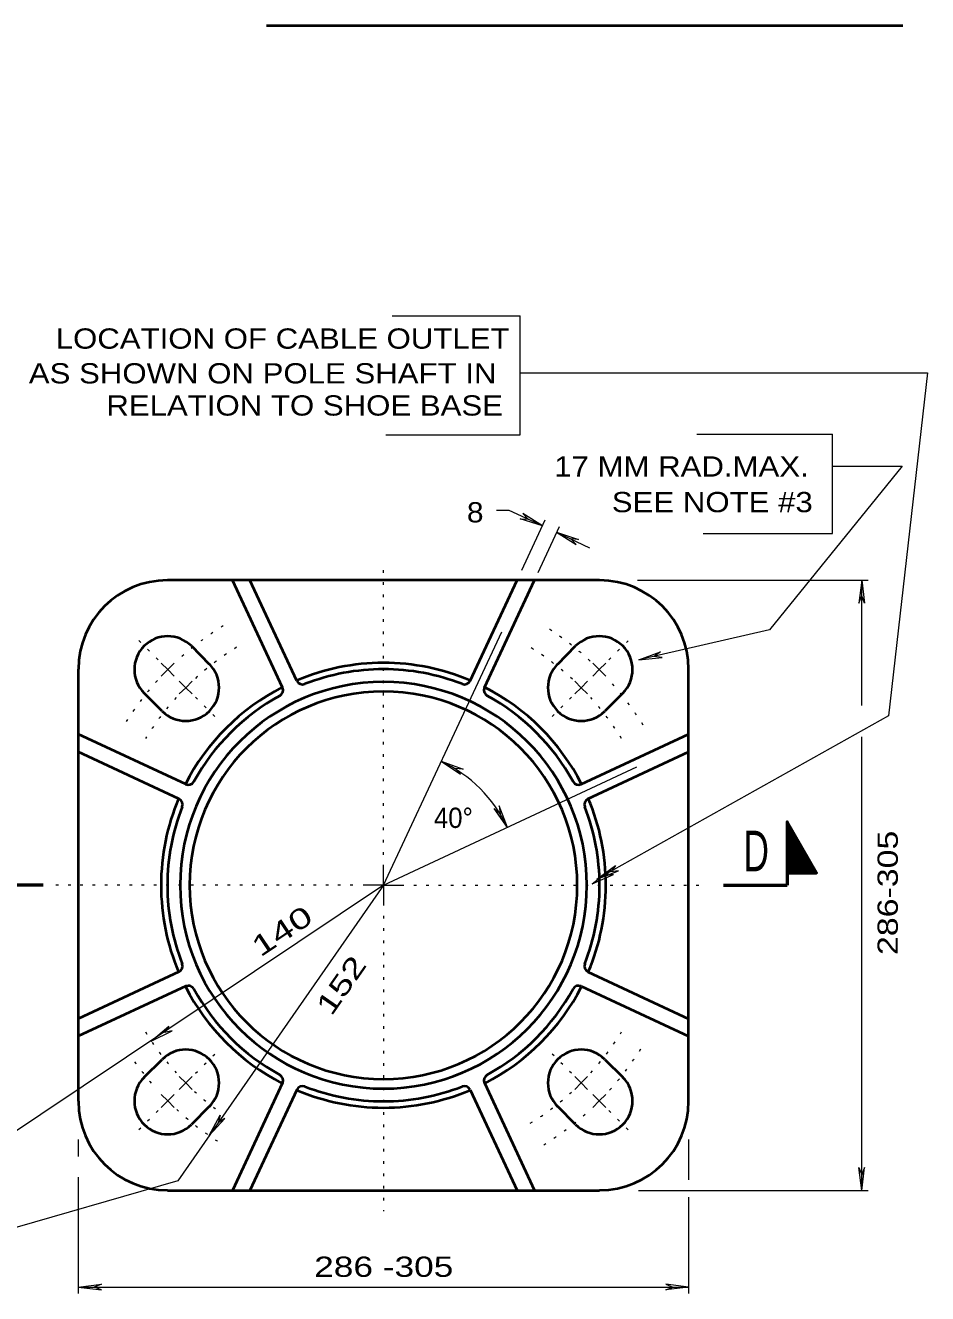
# Model space of a CAD drawing. Extents: x 312583 to 312854, y 144418 to 144597.
# Drawn here: x 312774.81 to 312808.64, y 144500.47 to 144548.02 of the extents above; entities that cross this region are included whole.
import ezdxf
from ezdxf.enums import TextEntityAlignment as Align

# ---------------------------------------------------------------- set-up
doc = ezdxf.new("R2010")
doc.units = 0
doc.header["$LTSCALE"] = 0.3
doc.linetypes.add('DOTTED', pattern=[1.5, 0.3, -1.2])
doc.layers.add('1', color=7, linetype='Continuous', lineweight=35)

msp = doc.modelspace()

# ---------------------------------------------------------------- linework, layer by layer
at = {"layer": '1', "lineweight": 40}
for p, q in [((312783.8489, 144548.0241), (312807.7021, 144548.0241)), ((312788.233, 144527.2141), (312780.1352, 144527.2141)), ((312784.451, 144523.1958), (312782.5752, 144527.2141)), ((312784.9924, 144523.4474), (312783.231, 144527.2141)), ((312796.3384, 144527.2141), (312788.233, 144527.2141)), ((312791.4812, 144523.4474), (312793.2426, 144527.2141)), ((312792.0226, 144523.1958), (312793.8984, 144527.2141)), ((312781.035, 144524.7512), (312781.706, 144524.0726)), ((312794.7676, 144524.0726), (312795.4386, 144524.7512)), ((312776.7955, 144523.882), (312776.7955, 144515.7766)), ((312799.6705, 144515.7766), (312799.6705, 144523.882)), ((312779.937, 144522.3036), (312779.266, 144522.9822)), ((312797.2076, 144522.9822), (312796.5366, 144522.3036)), ((312780.8215, 144519.5662), (312776.7955, 144521.442)), ((312795.6521, 144519.5662), (312799.6705, 144521.442)), ((312780.5699, 144519.0249), (312776.7955, 144520.7786)), ((312795.9038, 144519.0249), (312799.6705, 144520.7786)), ((312776.7955, 144515.7766), (312776.7955, 144507.6789)), ((312799.6705, 144507.6789), (312799.6705, 144515.7766)), ((312780.5699, 144512.5284), (312776.7955, 144510.7746)), ((312795.9038, 144512.5284), (312799.6705, 144510.7746)), ((312780.8215, 144511.9946), (312776.7955, 144510.1189)), ((312795.6521, 144511.9946), (312799.6705, 144510.1189)), ((312779.266, 144508.5786), (312779.937, 144509.2496)), ((312796.5366, 144509.2496), (312797.2076, 144508.5786)), ((312784.451, 144508.3651), (312782.5752, 144504.3391)), ((312784.9924, 144508.1059), (312783.231, 144504.3391)), ((312791.4812, 144508.1059), (312793.2426, 144504.3391)), ((312792.0226, 144508.3651), (312793.8984, 144504.3391)), ((312781.706, 144507.4806), (312781.035, 144506.8096)), ((312795.4386, 144506.8096), (312794.7676, 144507.4806)), ((312780.1352, 144504.3391), (312788.233, 144504.3391)), ((312788.233, 144504.3391), (312796.3384, 144504.3391))]:
    msp.add_line(p, q, dxfattribs=at)
at = {"layer": '1', "lineweight": 13}
for p, q in [((312788.5564, 144537.1328), (312793.3601, 144537.1328)), ((312793.3601, 144532.6645), (312793.3601, 144537.1328)), ((312793.3601, 144534.9992), (312808.6375, 144534.9992)), ((312788.3277, 144532.6645), (312793.3601, 144532.6645)), ((312799.9908, 144532.6965), (312805.069, 144532.6965)), ((312805.069, 144528.9679), (312805.069, 144532.6965)), ((312792.9529, 144529.8371), (312792.4725, 144529.8371)), ((312794.1958, 144529.2576), (312792.9529, 144529.8371)), ((312793.3646, 144529.5245), (312793.662, 144529.5092)), ((312794.1958, 144529.2576), (312793.3646, 144529.5245)), ((312793.418, 144527.5954), (312794.3025, 144529.4864)), ((312793.4561, 144529.7228), (312793.662, 144529.5092)), ((312794.1958, 144529.2576), (312793.4561, 144529.7228)), ((312794.0356, 144527.5039), (312794.8362, 144529.2348)), ((312794.7219, 144529.0136), (312795.9648, 144528.4341)), ((312794.7219, 144529.0136), (312795.553, 144528.7468)), ((312794.7219, 144529.0136), (312795.4615, 144528.5561)), ((312800.2271, 144528.9679), (312805.069, 144528.9679)), ((312795.553, 144528.7468), (312795.2556, 144528.7696)), ((312795.4615, 144528.5561), (312795.2556, 144528.7696)), ((312797.7642, 144527.2141), (312806.411, 144527.2141)), ((312806.167, 144527.2141), (312806.0602, 144526.3525)), ((312806.167, 144527.2141), (312806.2738, 144526.3525)), ((312806.167, 144522.5171), (312806.167, 144527.2141)), ((312806.0602, 144526.3525), (312806.167, 144526.627)), ((312806.2738, 144526.3525), (312806.167, 144526.627)), ((312788.233, 144515.7766), (312792.6708, 144525.2774)), ((312780.1505, 144523.8668), (312779.9065, 144524.1108)), ((312780.1505, 144523.8668), (312780.3945, 144524.1108)), ((312796.3231, 144523.8668), (312796.0868, 144524.1108)), ((312796.3231, 144523.8668), (312796.5671, 144524.1108)), ((312797.81, 144524.2328), (312798.6259, 144524.5301)), ((312797.81, 144524.2328), (312798.6792, 144524.3166)), ((312798.6259, 144524.5301), (312798.3819, 144524.3624)), ((312798.6792, 144524.3166), (312798.3819, 144524.3624)), ((312780.1505, 144523.8668), (312779.9065, 144523.6228)), ((312780.1505, 144523.8668), (312780.3945, 144523.6228)), ((312796.3231, 144523.8668), (312796.0868, 144523.6228)), ((312796.3231, 144523.8668), (312796.5671, 144523.6228)), ((312780.8215, 144523.1881), (312780.5775, 144523.4321)), ((312780.8215, 144523.1881), (312780.5775, 144522.9518)), ((312780.8215, 144523.1881), (312781.0655, 144523.4321)), ((312780.8215, 144523.1881), (312781.0655, 144522.9518)), ((312795.6521, 144523.1881), (312795.4081, 144523.4321)), ((312795.6521, 144523.1881), (312795.4081, 144522.9518)), ((312795.6521, 144523.1881), (312795.8885, 144523.4321)), ((312795.6521, 144523.1881), (312795.8885, 144522.9518)), ((312806.167, 144504.3391), (312806.167, 144521.3429)), ((312790.3985, 144520.4279), (312791.1229, 144519.9399)), ((312790.3985, 144520.4279), (312791.222, 144520.1305)), ((312788.233, 144515.7766), (312797.7414, 144520.2144)), ((312791.1229, 144519.9399), (312790.9246, 144520.1534)), ((312791.222, 144520.1305), (312790.9246, 144520.1534)), ((312792.381, 144518.6589), (312792.6098, 144518.4606)), ((312792.8842, 144517.9421), (312792.381, 144518.6589)), ((312792.5716, 144518.758), (312792.6098, 144518.4606)), ((312792.8842, 144517.9421), (312792.5716, 144518.758)), ((312788.233, 144515.7766), (312788.233, 144516.5391)), ((312796.2392, 144516.0054), (312796.9408, 144516.5162)), ((312796.9408, 144516.5162), (312796.7578, 144516.2875)), ((312796.0639, 144515.83), (312796.7425, 144516.3714)), ((312796.0639, 144515.83), (312796.8569, 144516.1884)), ((312796.2392, 144516.0054), (312797.0475, 144516.3256)), ((312796.7425, 144516.3714), (312796.5671, 144516.135)), ((312796.8569, 144516.1884), (312796.5671, 144516.135)), ((312797.0475, 144516.3256), (312796.7578, 144516.2875)), ((312788.233, 144515.7766), (312773.6388, 144506.0166)), ((312788.233, 144515.7766), (312780.5318, 144504.6975)), ((312788.233, 144515.7766), (312787.4705, 144515.7766)), ((312788.233, 144515.7766), (312788.9955, 144515.7766)), ((312788.233, 144515.7766), (312788.233, 144515.0141)), ((312779.5329, 144509.9282), (312780.1886, 144510.5001)), ((312779.5329, 144509.9282), (312780.3106, 144510.3248)), ((312780.1886, 144510.5001), (312780.0209, 144510.2561)), ((312780.3106, 144510.3248), (312780.0209, 144510.2561)), ((312780.8215, 144508.3651), (312780.5775, 144508.6091)), ((312780.8215, 144508.3651), (312781.0655, 144508.6091)), ((312795.6521, 144508.3651), (312795.4081, 144508.6091)), ((312795.6521, 144508.3651), (312795.8885, 144508.6091)), ((312780.1505, 144507.6941), (312779.9065, 144507.9305)), ((312780.1505, 144507.6941), (312780.3945, 144507.9305)), ((312780.8215, 144508.3651), (312780.5775, 144508.1211)), ((312780.8215, 144508.3651), (312781.0655, 144508.1211)), ((312795.6521, 144508.3651), (312795.4081, 144508.1211)), ((312795.6521, 144508.3651), (312795.8885, 144508.1211)), ((312796.3231, 144507.6941), (312796.0868, 144507.9305)), ((312796.3231, 144507.6941), (312796.5671, 144507.9305)), ((312780.1505, 144507.6941), (312779.9065, 144507.4501)), ((312780.1505, 144507.6941), (312780.3945, 144507.4501)), ((312796.3231, 144507.6941), (312796.0868, 144507.4501)), ((312796.3231, 144507.6941), (312796.5671, 144507.4501)), ((312781.706, 144506.3902), (312782.1101, 144507.1604)), ((312781.706, 144506.3902), (312782.2855, 144507.0384)), ((312782.1101, 144507.1604), (312782.0415, 144506.8706)), ((312782.2855, 144507.0384), (312782.0415, 144506.8706)), ((312776.7955, 144506.2454), (312776.7955, 144505.6049)), ((312799.6705, 144506.2454), (312799.6705, 144504.728)), ((312806.0602, 144505.2008), (312806.167, 144504.9262)), ((312806.167, 144504.3391), (312806.0602, 144505.2008)), ((312806.2738, 144505.2008), (312806.167, 144504.9262)), ((312806.167, 144504.3391), (312806.2738, 144505.2008)), ((312780.5318, 144504.6975), (312773.6388, 144502.7074)), ((312776.7955, 144504.8348), (312776.7955, 144500.4656)), ((312797.7948, 144504.3391), (312806.411, 144504.3391)), ((312799.6705, 144504.0799), (312799.6705, 144500.4656)), ((312776.7955, 144500.7096), (312777.6648, 144500.8164)), ((312777.6648, 144500.8164), (312777.3902, 144500.7096)), ((312798.8165, 144500.8164), (312799.091, 144500.7096)), ((312799.6705, 144500.7096), (312798.8165, 144500.8164)), ((312776.7955, 144500.7096), (312799.6705, 144500.7096)), ((312776.7955, 144500.7096), (312777.6648, 144500.6029)), ((312777.6648, 144500.6029), (312777.3902, 144500.7096)), ((312798.8165, 144500.6029), (312799.091, 144500.7096)), ((312799.6705, 144500.7096), (312798.8165, 144500.6029))]:
    msp.add_line(p, q, dxfattribs=at)
at = {"layer": '1', "linetype": 'DOTTED', "lineweight": 13}
for p, q in [((312788.233, 144516.9204), (312788.233, 144527.8851)), ((312779.7845, 144524.2328), (312779.022, 144524.9952)), ((312796.6891, 144524.2328), (312797.4592, 144524.9952)), ((312781.1875, 144522.8298), (312782.0491, 144521.9681)), ((312795.2861, 144522.8298), (312794.4245, 144521.9681)), ((312787.0892, 144515.7766), (312775.9262, 144515.7766)), ((312789.3768, 144515.7766), (312800.3262, 144515.7766)), ((312788.233, 144514.6329), (312788.233, 144503.5538)), ((312781.1875, 144508.7311), (312782.0491, 144509.5851)), ((312795.2861, 144508.7311), (312794.4245, 144509.5851)), ((312779.7845, 144507.3281), (312779.022, 144506.558)), ((312796.6891, 144507.3281), (312797.4592, 144506.558))]:
    msp.add_line(p, q, dxfattribs=at)
at = {"layer": '1'}
for p, q in [((312803.3686, 144518.1404), (312803.3839, 144518.1404)), ((312803.3686, 144518.1099), (312803.3915, 144518.1175)), ((312803.3686, 144518.0794), (312803.4068, 144518.1022)), ((312803.3686, 144518.0565), (312803.4144, 144518.0794)), ((312803.3686, 144518.026), (312803.4296, 144518.0565)), ((312803.3686, 144518.0031), (312803.4372, 144518.0412)), ((312803.3686, 144517.9726), (312803.4525, 144518.0184)), ((312803.3686, 144517.9421), (312803.4601, 144517.9955)), ((312803.3686, 144517.9116), (312803.4754, 144517.9802)), ((312803.3686, 144517.8888), (312803.483, 144517.9574)), ((312803.3686, 144517.8659), (312803.4982, 144517.9345)), ((312803.3686, 144517.8354), (312803.5059, 144517.9116)), ((312803.3686, 144517.8125), (312803.5211, 144517.8964)), ((312803.3686, 144517.782), (312803.5364, 144517.8735)), ((312803.3686, 144517.7515), (312803.544, 144517.8506)), ((312803.3686, 144517.721), (312803.5592, 144517.8354)), ((312803.3686, 144517.6981), (312803.5745, 144517.8125)), ((312803.3686, 144517.6676), (312803.5821, 144517.7896)), ((312803.3686, 144517.6448), (312803.5974, 144517.7744)), ((312803.3686, 144517.6142), (312803.605, 144517.7515)), ((312803.3686, 144517.5838), (312803.6202, 144517.7286)), ((312803.3686, 144517.5609), (312803.6279, 144517.7134)), ((312803.3686, 144517.5304), (312803.6431, 144517.6829)), ((312803.3686, 144517.5075), (312803.6508, 144517.6676)), ((312803.3686, 144517.477), (312803.666, 144517.6448)), ((312803.3686, 144517.4465), (312803.6736, 144517.6219)), ((312803.3686, 144517.4236), (312803.6889, 144517.6066)), ((312803.3686, 144517.3931), (312803.6965, 144517.5838)), ((312803.3686, 144517.3702), (312803.7118, 144517.5609)), ((312803.3686, 144517.3398), (312803.727, 144517.5456)), ((312803.3686, 144517.3169), (312803.7346, 144517.5228)), ((312803.3686, 144517.2864), (312803.7499, 144517.4999)), ((312803.3686, 144517.2559), (312803.7651, 144517.4846)), ((312803.3686, 144517.2254), (312803.7728, 144517.4618)), ((312803.3686, 144517.2025), (312803.788, 144517.4389)), ((312803.3686, 144517.1796), (312803.7956, 144517.416)), ((312803.3686, 144517.1491), (312803.8109, 144517.4008)), ((312803.3686, 144517.1186), (312803.8185, 144517.3779)), ((312803.3686, 144517.0958), (312803.8338, 144517.355)), ((312803.3686, 144517.0652), (312803.8414, 144517.3398)), ((312803.3686, 144517.0348), (312803.8566, 144517.3169)), ((312803.3686, 144517.0119), (312803.8642, 144517.294)), ((312803.3686, 144516.9814), (312803.8795, 144517.2788)), ((312803.3686, 144516.9509), (312803.8871, 144517.2559)), ((312803.3686, 144516.928), (312803.9024, 144517.233)), ((312803.3686, 144516.8746), (312803.9252, 144517.1872)), ((312803.3686, 144516.8441), (312803.9405, 144517.172)), ((312803.3686, 144516.8212), (312803.9481, 144517.1491)), ((312803.3686, 144516.7908), (312803.9634, 144517.1262)), ((312803.3686, 144516.7602), (312803.971, 144517.111)), ((312803.3686, 144516.7298), (312803.9862, 144517.0881)), ((312803.3686, 144516.7069), (312803.9939, 144517.0652)), ((312803.3686, 144516.684), (312804.0091, 144517.05)), ((312803.3686, 144516.623), (312804.032, 144517.0042)), ((312803.3686, 144516.6001), (312804.0396, 144516.989)), ((312803.3686, 144516.5696), (312804.0549, 144516.9661)), ((312803.3762, 144516.8975), (312803.9176, 144517.2178)), ((312803.3762, 144516.6535), (312804.0168, 144517.0271)), ((312803.3686, 144516.5391), (312804.0701, 144516.9432)), ((312803.3686, 144516.5162), (312804.0778, 144516.9204)), ((312803.3686, 144516.4858), (312804.093, 144516.9051)), ((312803.3686, 144516.4552), (312804.1082, 144516.8822)), ((312803.3686, 144516.379), (312804.1388, 144516.8212)), ((312803.3686, 144516.3485), (312804.154, 144516.7984)), ((312803.3686, 144516.3256), (312804.1616, 144516.7831)), ((312803.3686, 144516.2951), (312804.1769, 144516.7602)), ((312803.3686, 144516.2646), (312804.1845, 144516.7374)), ((312803.3762, 144516.4324), (312804.1159, 144516.8594)), ((312803.3762, 144516.4019), (312804.1311, 144516.8441)), ((312803.3915, 144516.2494), (312804.1998, 144516.7221)), ((312803.4449, 144516.2494), (312804.2074, 144516.6916)), ((312803.483, 144516.2494), (312804.2226, 144516.6764)), ((312803.5364, 144516.2494), (312804.2302, 144516.6535)), ((312803.5821, 144516.2494), (312804.2455, 144516.6306)), ((312803.6279, 144516.2494), (312804.2608, 144516.6154)), ((312803.6736, 144516.2494), (312804.2684, 144516.5925)), ((312803.727, 144516.2494), (312804.2836, 144516.5696)), ((312803.7728, 144516.2494), (312804.2989, 144516.5544)), ((312803.8185, 144516.2494), (312804.3065, 144516.5315)), ((312803.8719, 144516.2494), (312804.3218, 144516.5162)), ((312803.9176, 144516.2494), (312804.3294, 144516.4934)), ((312803.9634, 144516.2494), (312804.3446, 144516.4705)), ((312804.0168, 144516.2494), (312804.3522, 144516.4552)), ((312804.0625, 144516.2494), (312804.3675, 144516.4248)), ((312804.1082, 144516.2494), (312804.3751, 144516.4095)), ((312804.154, 144516.2494), (312804.3904, 144516.3866)), ((312804.2074, 144516.2494), (312804.398, 144516.3638)), ((312804.2455, 144516.2494), (312804.4132, 144516.3485)), ((312804.2989, 144516.2494), (312804.4209, 144516.3256)), ((312804.3446, 144516.2494), (312804.4361, 144516.3028)), ((312804.398, 144516.2494), (312804.4514, 144516.2875)), ((312804.4438, 144516.2494), (312804.459, 144516.2646))]:
    msp.add_line(p, q, dxfattribs=at)
at = {"layer": '1', "lineweight": 53}
for p, q in [((312803.3686, 144516.2494), (312803.3686, 144515.7766)), ((312775.484, 144515.7766), (312773.105, 144515.7766)), ((312800.9896, 144515.7766), (312803.3686, 144515.7766))]:
    msp.add_line(p, q, dxfattribs=at)
at = {"layer": '1', "lineweight": 13}
for points in [[(312808.6375, 144534.9992), (312807.1735, 144522.1359), (312796.2392, 144516.0054)], [(312805.069, 144531.4994), (312807.6844, 144531.4994), (312802.7052, 144525.3536), (312797.81, 144524.2328)]]:
    msp.add_lwpolyline(points, dxfattribs=at)
at = {"layer": '1', "lineweight": 53}
msp.add_lwpolyline([(312803.3686, 144516.2494), (312804.4742, 144516.2494), (312803.3686, 144518.1556)], close=True, dxfattribs=at)
at = {"layer": '1', "lineweight": 40}
for centre, radius, start, end in [((312780.1352, 144523.8801), 3.3359, 90, 180), ((312796.3384, 144523.8801), 3.3359, 0, 90), ((312780.1486, 144523.8667), 1.251, 45, 225), ((312796.325, 144523.8667), 1.251, 315, 135), ((312788.2368, 144515.7785), 8.3398, 90, 112.94673), ((312788.2368, 144515.7785), 8.3398, 67.05327, 90), ((312780.8234, 144523.1919), 1.251, 225, 45), ((312788.2368, 144515.7785), 8.1016, 90, 111.30566), ((312788.2368, 144515.7785), 8.1016, 68.69434, 90), ((312795.6502, 144523.1919), 1.251, 135, 315), ((312788.2368, 144515.7785), 7.625, 90, 180), ((312788.2368, 144515.7785), 8.3398, 117.05705, 152.95096), ((312784.2334, 144523.0946), 0.2383, 298.68804, 25.01264), ((312785.2064, 144523.5483), 0.2383, 205.00333, 291.30722), ((312788.2368, 144515.7785), 7.625, 0, 90), ((312791.2673, 144523.5483), 0.2383, 248.69278, 334.99667), ((312792.2403, 144523.0946), 0.2383, 154.98736, 241.31196), ((312788.2368, 144515.7785), 8.3398, 27.05705, 62.95096), ((312788.2368, 144515.7785), 7.2676, 90, 180), ((312788.2368, 144515.7785), 8.1016, 118.68793, 151.31207), ((312788.2368, 144515.7785), 7.2676, 0, 90), ((312788.2368, 144515.7785), 8.1016, 28.68793, 61.31207), ((312780.9207, 144519.782), 0.2383, 244.98736, 331.31196), ((312795.5529, 144519.782), 0.2383, 208.68804, 295.01264), ((312788.2368, 144515.7785), 8.3398, 157.05327, 180), ((312780.467, 144518.809), 0.2383, 338.69278, 64.99667), ((312796.0066, 144518.809), 0.2383, 115.00333, 201.30722), ((312788.2368, 144515.7785), 8.3398, 0, 22.94673), ((312788.2368, 144515.7785), 8.1016, 158.69434, 180), ((312788.2368, 144515.7785), 8.1016, 0, 21.30566), ((312788.2368, 144515.7785), 8.3398, 180, 202.94673), ((312788.2368, 144515.7785), 8.1016, 180, 201.30566), ((312788.2368, 144515.7785), 7.625, 180, 270), ((312788.2368, 144515.7785), 7.2676, 180, 270), ((312788.2368, 144515.7785), 7.625, 270, 0), ((312788.2368, 144515.7785), 7.2676, 270, 0), ((312788.2368, 144515.7785), 8.1016, 338.69434, 0), ((312788.2368, 144515.7785), 8.3398, 337.05327, 0), ((312780.467, 144512.7481), 0.2383, 295.00333, 21.30722), ((312796.0066, 144512.7481), 0.2383, 158.69278, 244.99667), ((312788.2368, 144515.7785), 8.3398, 207.05705, 242.95096), ((312780.9207, 144511.7751), 0.2383, 28.68804, 115.01264), ((312788.2368, 144515.7785), 8.1016, 208.68793, 241.31207), ((312788.2368, 144515.7785), 8.3398, 297.05705, 332.95096), ((312788.2368, 144515.7785), 8.1016, 298.68793, 331.31207), ((312795.5529, 144511.7751), 0.2383, 64.98736, 151.31196), ((312780.8234, 144508.3651), 1.251, 315, 135), ((312795.6502, 144508.3651), 1.251, 45, 225), ((312780.1486, 144507.6903), 1.251, 135, 315), ((312784.2334, 144508.4624), 0.2383, 334.98736, 61.31196), ((312792.2403, 144508.4624), 0.2383, 118.68804, 205.01264), ((312796.325, 144507.6903), 1.251, 225, 45), ((312788.2368, 144515.7785), 8.3398, 247.05327, 270), ((312785.2064, 144508.0088), 0.2383, 68.69278, 154.99667), ((312788.2368, 144515.7785), 8.1016, 248.69434, 270), ((312788.2368, 144515.7785), 8.1016, 270, 291.30566), ((312788.2368, 144515.7785), 8.3398, 270, 292.94673), ((312791.2673, 144508.0088), 0.2383, 25.00333, 111.30722), ((312780.1352, 144507.677), 3.3359, 180, 270), ((312796.3384, 144507.677), 3.3359, 270, 0)]:
    msp.add_arc(centre, radius, start, end, dxfattribs=at)
at = {"layer": '1', "linetype": 'DOTTED', "lineweight": 13}
for radius, start, end in [(11.4375, 121.67302, 132.67646), (11.4375, 47.32354, 58.32698), (10.4844, 121.67021, 132.50277), (10.4844, 47.49723, 58.32979), (11.4375, 137.83702, 148.35019), (11.4375, 31.64981, 42.16298), (10.4844, 137.83921, 148.35431), (10.4844, 31.64569, 42.16079), (10.4844, 211.64569, 222.16079), (10.4844, 317.83921, 328.35431), (11.4375, 317.83702, 328.35019), (11.4375, 215.3347, 222.16255), (10.4844, 227.49787, 233.37708), (10.4844, 301.67021, 312.50277), (11.4375, 227.32354, 238.32698), (11.4375, 301.67302, 312.67646)]:
    msp.add_arc((312788.2368, 144515.7785), radius, start, end, dxfattribs=at)
at = {"layer": '1', "lineweight": 13}
msp.add_arc((312788.2368, 144515.7785), 5.1256, 25.00431, 65.00757, dxfattribs=at)

# ---------------------------------------------------------------- texts
at = {"layer": '1'}
for s, width, p in [('LOCATION OF CABLE OUTLET', 1.15, (312775.9479, 144535.9)), ('AS SHOWN ON POLE SHAFT IN', 1.15, (312774.9398, 144534.5964)), ('RELATION TO SHOE BASE', 1.15, (312777.846, 144533.3914)), ('17 MM RAD.MAX.', 1.15, (312794.6364, 144531.1033)), ('SEE NOTE #3', 1.15, (312796.7962, 144529.7681)), ('8 ', 1.1, (312791.3652, 144529.3856)), ('40°', 0.95, (312790.1276, 144517.9284)), ('286 -305 ', 1.3, (312785.6382, 144501.0947))]:
    msp.add_text(s, height=0.76, dxfattribs=dict(at, width=width)).set_placement(p)
at = {"layer": '1', "width": 0.65}
msp.add_text('D', height=1.525, dxfattribs=at).set_placement((312802.2096, 144516.3028), align=Align.CENTER)
at = {"layer": '1'}
for s, rotation, width, p in [('286-305 ', 90, 1.25, (312807.5202, 144513.1633)), ('140 ', 33.904, 1.45, (312783.6218, 144513.0632)), ('152 ', 55.183, 1.4, (312786.2843, 144510.84))]:
    msp.add_text(s, height=0.76, rotation=rotation, dxfattribs=dict(at, width=width)).set_placement(p)

doc.saveas('drawing.dxf')
